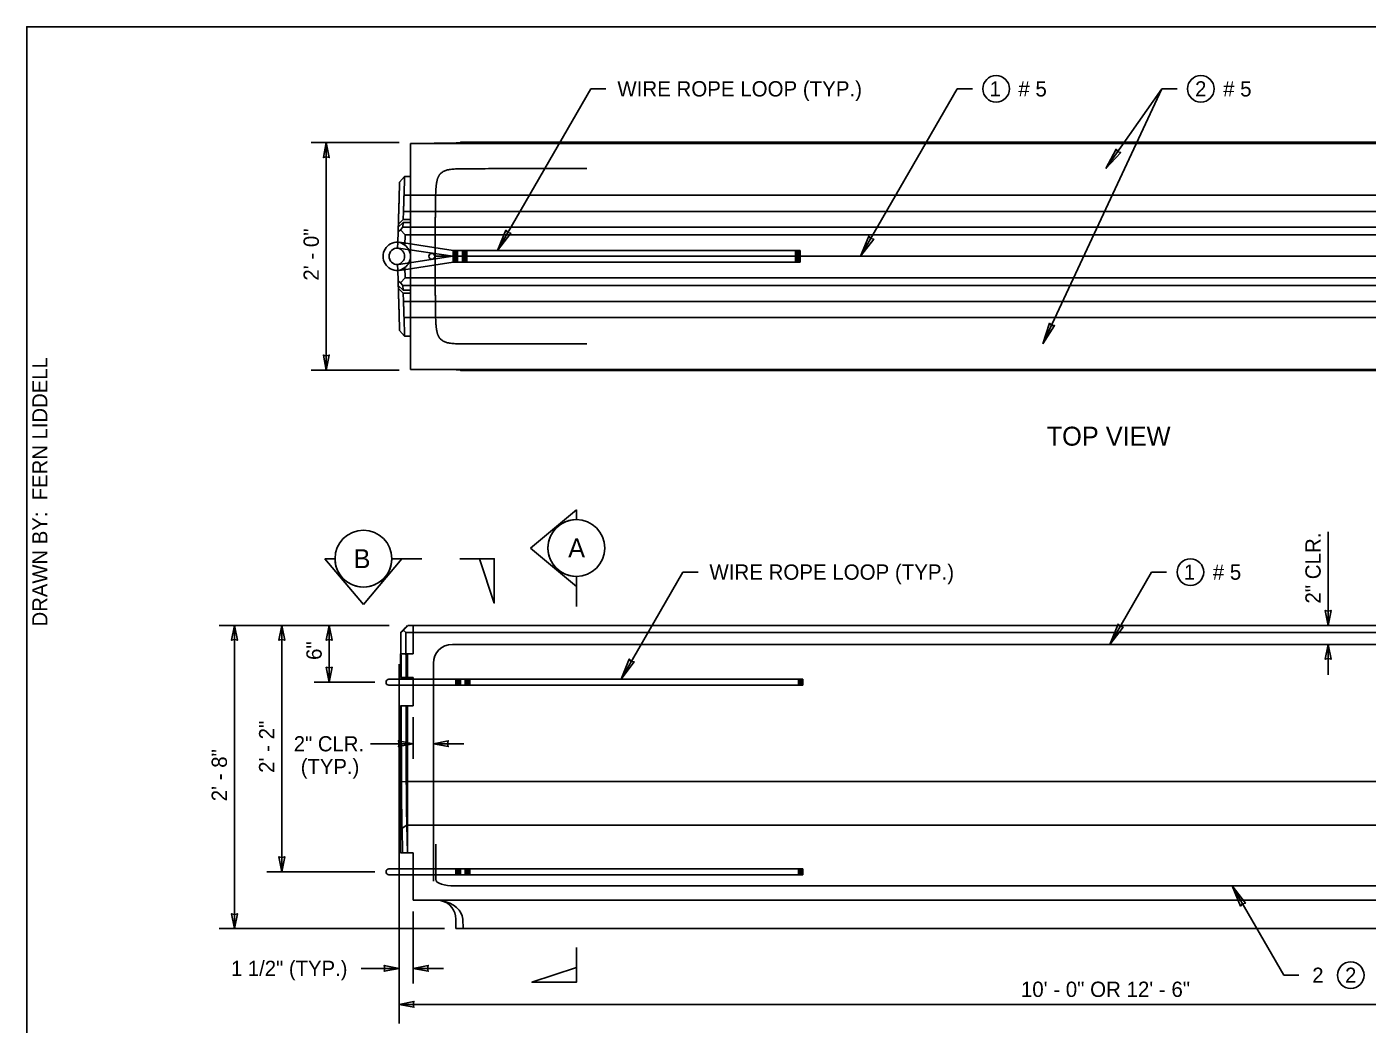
# Model space of a CAD drawing. Extents: x 99862 to 103680, y 99470 to 105076.
# Drawn here: x 99862 to 101262, y 101033 to 102076 of the extents above; entities that cross this region are included whole.
import ezdxf

# ---------------------------------------------------------------- set-up
doc = ezdxf.new("R2010")
doc.units = 0
for name, color, linetype in [('Level 1', 7, 'Continuous'), ('Level 15', 7, 'Continuous'), ('Level 17', 7, 'Continuous'), ('Level 20', 7, 'Continuous'), ('Level 27', 7, 'Continuous'), ('Level 62', 7, 'Continuous'), ('Level 9', 7, 'Continuous')]:
    doc.layers.add(name, color=color, linetype=linetype)

msp = doc.modelspace()

# ---------------------------------------------------------------- linework, layer by layer
at = {"layer": 'Level 1'}
for p, q in [((100262.8, 101919.2), (100262.8, 101953.7)), ((100251.5, 101913.2), (100251, 101895.4)), ((100256.6, 101919.2), (100251.5, 101913.2)), ((100256.1, 101899.4), (100256.6, 101919.2)), ((100256.6, 101919.2), (100262.8, 101919.2)), ((100255.3, 101874.2), (100255.5, 101882.6)), ((100250.1, 101866.1), (100249.9, 101861.2)), ((100255.2, 101871.1), (100250.1, 101866.1)), ((100250.2, 101869.3), (100250.1, 101866.1)), ((100250.4, 101877.6), (100250.2, 101869.3)), ((100250.2, 101869.3), (100255.3, 101874.2)), ((100255, 101866.2), (100252.5, 101863.4)), ((100255, 101866.2), (100255.2, 101871.1)), ((100255.2, 101871.1), (100262.8, 101871.1)), ((100262.8, 101874.2), (100255.3, 101874.2)), ((100262.8, 101871.1), (100262.8, 101874.2)), ((100249.6, 101850.4), (100249.9, 101861.2)), ((100249.9, 101861.2), (100252.5, 101863.4)), ((100252.5, 101863.4), (100257.3, 101858)), ((100257.3, 101858), (100257, 101847.5)), ((100249.6, 101850.4), (100249.4, 101844.2)), ((100249.6, 101820.9), (100249.4, 101827.2)), ((100257, 101823.9), (100257.3, 101813.4)), ((100249.9, 101810.2), (100249.6, 101820.9)), ((100249.9, 101810.2), (100250.1, 101805.2)), ((100252.5, 101807.9), (100249.9, 101810.2)), ((100252.5, 101807.9), (100257.3, 101813.4)), ((100250.2, 101802.1), (100250.1, 101805.2)), ((100255.2, 101800.3), (100250.1, 101805.2)), ((100250.2, 101802.1), (100250.4, 101793.7)), ((100250.2, 101802.1), (100255.3, 101797.1)), ((100255, 101805.2), (100252.5, 101807.9)), ((100255.2, 101800.3), (100255, 101805.2)), ((100262.8, 101800.3), (100255.2, 101800.3)), ((100255.5, 101788.8), (100255.3, 101797.1)), ((100255.3, 101797.1), (100262.8, 101797.1)), ((100262.8, 101797.1), (100262.8, 101800.3)), ((100251, 101776), (100251.5, 101758.2)), ((100256.6, 101752.2), (100256.1, 101771.9)), ((100256.6, 101752.2), (100251.5, 101758.2)), ((100262.8, 101752.2), (100256.6, 101752.2)), ((100262.8, 101717.6), (100262.8, 101752.2)), ((100255.5, 101445.2), (100260.3, 101450.1)), ((100260, 101450.1), (100260.3, 101450.1)), ((100252.9, 101442.7), (100252.6, 101442.7)), ((100255.5, 101445.2), (100252.9, 101442.7)), ((100258, 101442.7), (100255.5, 101445.2))]:
    msp.add_line(p, q, dxfattribs=at)
msp.add_lwpolyline([(99862, 99999.5), (103151, 99999.5), (103151, 102075.5), (99862, 102075.5)], close=True, dxfattribs=at)
for centre, radius, start, end in [((100249.2, 101835.7), 14.9, 88.3026, 271.6974), ((100249.2, 101835.7), 8.66, 88.3024, 180), ((100248, 101835.7), 8.66, 279.9067, 80.0933), ((100248, 101835.7), 14.8, 52.6201, 83.5248), ((100248, 101835.7), 14.8, 307.3799, 52.6201), ((100249.2, 101835.7), 8.66, 180, 271.6976), ((100248, 101835.7), 14.8, 276.4752, 307.3799)]:
    msp.add_arc(centre, radius, start, end, dxfattribs=at)
msp.add_ellipse((100250.9, 101441.4), major_axis=(-14.8, -14.8), ratio=0.014812, start_param=1.669, end_param=2.208388, dxfattribs=at)
for points in [[(100250.4, 101877.6), (100250.5, 101879.4), (100250.7, 101885.6), (100251, 101895.4)], [(100256.1, 101899.4), (100255.8, 101890.1), (100255.6, 101884.3), (100255.5, 101882.6)], [(100251, 101776), (100250.7, 101785.8), (100250.5, 101791.9), (100250.4, 101793.7)], [(100255.5, 101788.8), (100255.6, 101787.1), (100255.8, 101781.3), (100256.1, 101771.9)]]:
    msp.add_open_spline(points, degree=2, dxfattribs=at)
at = {"layer": 'Level 15'}
for p, q in [((100353.8, 101841.9), (100451.2, 102010.7)), ((100451.2, 102010.7), (100467.1, 102010.7)), ((100733, 101835.7), (100834, 102010.7)), ((100849.9, 102010.7), (100834, 102010.7)), ((100923.6, 101744.1), (101047.9, 102010.7)), ((100989.5, 101927.3), (101047.9, 102010.7)), ((101063.7, 102010.7), (101047.9, 102010.7)), ((100159.1, 101954.5), (100250.9, 101954.5)), ((100174.9, 101954.5), (100174.9, 101716.9)), ((100159.1, 101716.9), (100250.9, 101716.9)), ((101221.6, 101450.1), (101221.6, 101547.7)), ((100482.8, 101393.8), (100547.4, 101505.8)), ((100547.4, 101505.8), (100563.3, 101505.8)), ((100993.4, 101430.3), (101037.1, 101505.8)), ((101052.9, 101505.8), (101037.1, 101505.8)), ((100063.1, 101450.1), (100240.7, 101450.1)), ((100078.9, 101450.1), (100078.9, 101133.3)), ((100128.4, 101450.1), (100128.4, 101192.7)), ((100177.9, 101450.1), (100177.9, 101390.7)), ((101221.6, 101398.6), (101221.6, 101430.3)), ((100250.9, 101034.3), (100250.9, 101409.6)), ((100162.1, 101390.7), (100225.5, 101390.7)), ((100265.8, 101354.1), (100265.8, 101310.6)), ((100265.8, 101326.4), (100221.2, 101326.4)), ((100318.5, 101326.4), (100286.8, 101326.4)), ((100112.6, 101192.7), (100225.5, 101192.7)), ((101175.2, 101084.6), (101121.4, 101177.9)), ((100265.8, 101151.1), (100265.8, 101076)), ((100298.5, 101133.3), (100063.1, 101133.3)), ((100211.3, 101091.8), (100250.9, 101091.8)), ((100265.8, 101091.8), (100297.5, 101091.8)), ((101191, 101084.6), (101175.2, 101084.6)), ((100250.9, 101054.1), (101735.9, 101054.1))]:
    msp.add_line(p, q, dxfattribs=at)
for points in [[(100174.9, 101954.5), (100171.9, 101938.9), (100174.9, 101939.6), (100178, 101938.9)], [(100989.5, 101927.3), (101000, 101947.5), (101001.8, 101944.9), (101004.9, 101944.1)], [(100353.8, 101841.9), (100362.5, 101862.9), (100364.5, 101860.5), (100367.6, 101860)], [(100733, 101835.7), (100741.7, 101856.7), (100743.8, 101854.4), (100746.9, 101853.8)], [(100923.6, 101744.1), (100930.4, 101765.8), (100932.7, 101763.6), (100935.8, 101763.3)], [(100174.9, 101716.9), (100171.9, 101732.5), (100174.9, 101731.7), (100178, 101732.5)], [(101221.6, 101450.1), (101224.7, 101465.7), (101221.6, 101465), (101218.6, 101465.7)], [(100078.9, 101450.1), (100075.9, 101434.5), (100078.9, 101435.3), (100082, 101434.5)], [(100128.4, 101450.1), (100125.4, 101434.5), (100128.4, 101435.3), (100131.5, 101434.5)], [(100177.9, 101450.1), (100174.9, 101434.5), (100177.9, 101435.3), (100181, 101434.5)], [(100993.4, 101430.3), (101002.2, 101451.4), (101004.2, 101449), (101007.3, 101448.4)], [(101221.6, 101430.3), (101224.7, 101414.7), (101221.6, 101415.5), (101218.6, 101414.7)], [(100177.9, 101390.7), (100174.9, 101406.3), (100177.9, 101405.6), (100181, 101406.3)], [(100482.8, 101393.8), (100491.5, 101414.9), (100493.5, 101412.5), (100496.6, 101411.9)], [(100265.8, 101326.4), (100250.2, 101323.4), (100251, 101326.4), (100250.2, 101329.5)], [(100286.8, 101326.4), (100302.4, 101323.4), (100301.7, 101326.4), (100302.4, 101329.5)], [(100128.4, 101192.7), (100125.4, 101208.3), (100128.4, 101207.6), (100131.5, 101208.3)], [(101121.4, 101177.9), (101130.1, 101156.8), (101132.1, 101159.2), (101135.2, 101159.8)], [(100078.9, 101133.3), (100075.9, 101148.9), (100078.9, 101148.2), (100082, 101148.9)], [(100250.9, 101091.8), (100235.4, 101088.8), (100236.1, 101091.8), (100235.4, 101094.9)], [(100265.8, 101091.8), (100281.4, 101088.8), (100280.6, 101091.8), (100281.4, 101094.9)], [(100250.9, 101054.1), (100266.5, 101051.1), (100265.8, 101054.1), (100266.5, 101057.2)]]:
    msp.add_lwpolyline(points, close=True, dxfattribs=at)
at = {"layer": 'Level 17'}
for p, q in [((100287.7, 101953.7), (100262.8, 101953.7)), ((100287.7, 101953.7), (101699.2, 101953.7)), ((100314.6, 101954.6), (100315, 101955)), ((100315, 101955), (101671.9, 101955)), ((100255, 101866.3), (101731.9, 101866.3)), ((101729.6, 101858.1), (100257.3, 101858.1)), ((100257.3, 101813.3), (101729.6, 101813.3)), ((101731.9, 101805.1), (100255, 101805.1)), ((100287.7, 101717.6), (100262.8, 101717.6)), ((100287.7, 101717.6), (101699.2, 101717.6)), ((100314.6, 101716.8), (100315, 101716.4)), ((100315, 101716.4), (101671.9, 101716.4)), ((100260.3, 101450.1), (101726.6, 101450.1)), ((100252.6, 101442.7), (100252.6, 101420.4)), ((100252.9, 101442.7), (100253.1, 101395.7)), ((101728.9, 101442.7), (100258, 101442.7)), ((100258.2, 101395.7), (100258, 101442.7)), ((100252.6, 101420.4), (100252.4, 101420.4)), ((100252.4, 101420.4), (100252.4, 101395.7)), ((100240.4, 101393.8), (100253.9, 101393.8)), ((100252.4, 101395.7), (100253.1, 101395.7)), ((100258.2, 101395.7), (100253.1, 101395.7)), ((100265.8, 101393.8), (100253.9, 101393.8)), ((100265.8, 101395.7), (100258.2, 101395.7)), ((100265.8, 101366), (100265.8, 101395.7)), ((100253.9, 101387.6), (100240.4, 101387.6)), ((100253.9, 101387.6), (100265.8, 101387.6)), ((100253.2, 101366), (100252.4, 101366)), ((100252.4, 101366), (100252.4, 101212.5)), ((100253.2, 101366), (100258.3, 101366)), ((100253.2, 101366), (100253.4, 101286.5)), ((100258.3, 101366), (100265.8, 101366)), ((100258.5, 101287), (100258.3, 101366)), ((100258.5, 101287), (100253.4, 101286.5)), ((100259, 101241.3), (100254, 101238.4)), ((100254, 101238.4), (100254.5, 101212.5)), ((100259.6, 101212.5), (100259, 101241.3)), ((100252.4, 101212.5), (100254.5, 101212.5)), ((100259.6, 101212.5), (100254.5, 101212.5)), ((100265.8, 101212.5), (100259.6, 101212.5)), ((100265.8, 101163), (100265.8, 101212.5)), ((100240.4, 101195.8), (100253.9, 101195.8)), ((100265.8, 101195.8), (100253.9, 101195.8)), ((100253.9, 101189.6), (100240.4, 101189.6)), ((100253.9, 101189.6), (100265.8, 101189.6)), ((100290.5, 101163), (100265.8, 101163)), ((100290.5, 101163), (101696.3, 101163)), ((100310.3, 101133.3), (100310.3, 101143.2)), ((100317.4, 101143.2), (100317.8, 101133.3)), ((100317.8, 101133.3), (100310.3, 101133.3)), ((100317.8, 101133.3), (101669.1, 101133.3))]:
    msp.add_line(p, q, dxfattribs=at)
for centre, radius, start, end in [((100240.4, 101390.7), 3.09, 90, 270), ((100240.4, 101192.7), 3.09, 90, 270), ((100290.5, 101143.2), 19.8, 75.9627, 90), ((100290.5, 101143.2), 19.8, 0, 75.9627)]:
    msp.add_arc(centre, radius, start, end, dxfattribs=at)
for centre, major_axis, ratio, start_param, end_param in [((100287.7, 101954.6), (-19.9, 0), 0.041667, 1.570796, 1.815794), ((100286.5, 101954.6), (-28.1, 0), 0.029437, 1.786314, 3.112113), ((100287.7, 101716.8), (-19.9, 0), 0.041667, 4.467391, 4.712389), ((100286.5, 101716.8), (-28.1, 0), 0.029437, 3.171072, 4.496871), ((100289.4, 101143.2), (-28, 1.2), 0.705883, 3.200349, 4.526147)]:
    msp.add_ellipse(centre, major_axis=major_axis, ratio=ratio, start_param=start_param, end_param=end_param, dxfattribs=at)
for points in [[(100254, 101238.4), (100253.7, 101252.6), (100253.5, 101269.3), (100253.4, 101286.5)], [(100258.5, 101287), (100258.6, 101270.7), (100258.8, 101254.8), (100259, 101241.3)]]:
    msp.add_open_spline(points, degree=2, dxfattribs=at)
at = {"layer": 'Level 20'}
for centre in [(100874.7, 102010.7), (101088.6, 102010.7), (101077.7, 101505.8), (101245.2, 101084.6)]:
    msp.add_circle(centre, 13.9, dxfattribs=at)
at = {"layer": 'Level 27'}
for p, q in [((100256, 101899.7), (101730.9, 101899.7)), ((100255.5, 101882.7), (101731.4, 101882.7)), ((100255.5, 101788.6), (101731.4, 101788.6)), ((100256, 101771.7), (101730.9, 101771.7)), ((100258.5, 101287), (101728.4, 101287)), ((100259, 101241.3), (101727.8, 101241.3))]:
    msp.add_line(p, q, dxfattribs=at)
at = {"layer": 'Level 9'}
for p, q in [((100262.8, 101919.2), (100262.8, 101752.2)), ((100250.5, 101844.3), (100307.1, 101835.7)), ((100307.6, 101841.9), (100251.4, 101850.4)), ((100307.4, 101841.9), (100307.4, 101835.7)), ((100669.9, 101841.9), (100307.6, 101841.9)), ((100307.9, 101841.9), (100307.9, 101835.7)), ((100308.5, 101841.9), (100308.5, 101835.7)), ((100309.1, 101841.9), (100309.1, 101835.7)), ((100309.7, 101841.9), (100309.7, 101835.7)), ((100310.3, 101841.9), (100310.3, 101835.7)), ((100310.9, 101841.9), (100310.9, 101835.7)), ((100311.5, 101841.9), (100311.5, 101835.7)), ((100312.1, 101841.9), (100312.1, 101835.7)), ((100317.1, 101841.9), (100317.1, 101835.7)), ((100317.6, 101841.9), (100317.6, 101835.7)), ((100318.2, 101841.9), (100318.2, 101835.7)), ((100318.8, 101841.9), (100318.8, 101835.7)), ((100319.4, 101841.9), (100319.4, 101835.7)), ((100320, 101841.9), (100320, 101835.7)), ((100320.6, 101841.9), (100320.6, 101835.7)), ((100321.2, 101841.9), (100321.2, 101835.7)), ((100321.8, 101841.9), (100321.8, 101835.7)), ((100665.2, 101841.9), (100665.2, 101835.7)), ((100665.8, 101841.9), (100665.8, 101835.7)), ((100666.4, 101841.9), (100666.4, 101835.7)), ((100667, 101841.9), (100667, 101835.7)), ((100667.6, 101841.9), (100667.6, 101835.7)), ((100668.2, 101841.9), (100668.2, 101835.7)), ((100668.8, 101841.9), (100668.8, 101835.7)), ((100669.3, 101841.9), (100669.3, 101835.7)), ((100669.9, 101841.9), (100669.9, 101835.7)), ((100307, 101835.7), (100250.5, 101827.1)), ((100251.4, 101821), (100307.6, 101829.5)), ((100288.3, 101835.7), (101698.6, 101835.7)), ((100307.4, 101835.7), (100307.4, 101829.5)), ((100669.9, 101829.5), (100307.6, 101829.5)), ((100307.9, 101835.7), (100307.9, 101829.5)), ((100308.5, 101835.7), (100308.5, 101829.5)), ((100309.1, 101835.7), (100309.1, 101829.5)), ((100309.7, 101835.7), (100309.7, 101829.5)), ((100310.3, 101835.7), (100310.3, 101829.5)), ((100310.9, 101835.7), (100310.9, 101829.5)), ((100311.5, 101835.7), (100311.5, 101829.5)), ((100312.1, 101835.7), (100312.1, 101829.5)), ((100317.1, 101835.7), (100317.1, 101829.5)), ((100317.6, 101835.7), (100317.6, 101829.5)), ((100318.2, 101835.7), (100318.2, 101829.5)), ((100318.8, 101835.7), (100318.8, 101829.5)), ((100319.4, 101835.7), (100319.4, 101829.5)), ((100320, 101835.7), (100320, 101829.5)), ((100320.6, 101835.7), (100320.6, 101829.5)), ((100321.2, 101835.7), (100321.2, 101829.5)), ((100321.8, 101835.7), (100321.8, 101829.5)), ((100665.2, 101835.7), (100665.2, 101829.5)), ((100665.8, 101835.7), (100665.8, 101829.5)), ((100666.4, 101835.7), (100666.4, 101829.5)), ((100667, 101835.7), (100667, 101829.5)), ((100667.6, 101835.7), (100667.6, 101829.5)), ((100668.2, 101835.7), (100668.2, 101829.5)), ((100668.8, 101835.7), (100668.8, 101829.5)), ((100669.3, 101835.7), (100669.3, 101829.5)), ((100669.9, 101835.7), (100669.9, 101829.5)), ((100436.2, 101571), (100388.3, 101530.9)), ((100436.2, 101560.6), (100436.2, 101571)), ((100388.3, 101530.9), (100436.2, 101490.7)), ((100184, 101519.8), (100173.5, 101519.8)), ((100173.5, 101519.8), (100213.7, 101471.9)), ((100213.7, 101471.9), (100253.9, 101519.8)), ((100253.9, 101519.8), (100243.4, 101519.8)), ((100245, 101519.8), (100274.7, 101519.8)), ((100314.3, 101519.8), (100350.4, 101519.8)), ((100436.2, 101490.7), (100436.2, 101501.2)), ((100436.2, 101499.6), (100436.2, 101469.9)), ((100265.8, 101420.4), (100265.8, 101450.1)), ((100252.6, 101420.4), (100252.4, 101420.4)), ((100265.8, 101420.4), (100252.6, 101420.4)), ((100259.6, 101395.7), (100259.6, 101420.4)), ((100306.6, 101430.3), (101680.3, 101430.3)), ((100286.8, 101182.8), (100286.8, 101410.5)), ((100259.6, 101395.7), (100252.4, 101395.7)), ((100672.9, 101393.8), (100265.8, 101393.8)), ((100310.3, 101393.8), (100310.3, 101387.6)), ((100310.9, 101393.8), (100310.9, 101387.6)), ((100311.5, 101393.8), (100311.5, 101387.6)), ((100312.1, 101393.8), (100312.1, 101387.6)), ((100312.7, 101393.8), (100312.7, 101387.6)), ((100313.3, 101393.8), (100313.3, 101387.6)), ((100313.9, 101393.8), (100313.9, 101387.6)), ((100314.5, 101393.8), (100314.5, 101387.6)), ((100315.1, 101393.8), (100315.1, 101387.6)), ((100320, 101393.8), (100320, 101387.6)), ((100320.6, 101393.8), (100320.6, 101387.6)), ((100321.2, 101393.8), (100321.2, 101387.6)), ((100321.8, 101393.8), (100321.8, 101387.6)), ((100322.4, 101393.8), (100322.4, 101387.6)), ((100323, 101393.8), (100323, 101387.6)), ((100323.6, 101393.8), (100323.6, 101387.6)), ((100324.2, 101393.8), (100324.2, 101387.6)), ((100324.8, 101393.8), (100324.8, 101387.6)), ((100668.2, 101393.8), (100668.2, 101387.6)), ((100668.8, 101393.8), (100668.8, 101387.6)), ((100669.4, 101393.8), (100669.4, 101387.6)), ((100670, 101393.8), (100670, 101387.6)), ((100670.6, 101393.8), (100670.6, 101387.6)), ((100671.2, 101393.8), (100671.2, 101387.6)), ((100671.7, 101393.8), (100671.7, 101387.6)), ((100672.3, 101393.8), (100672.3, 101387.6)), ((100672.9, 101387.6), (100672.9, 101393.8)), ((100672.9, 101393.8), (100672.9, 101387.6)), ((100672.9, 101387.6), (100265.8, 101387.6)), ((100259.6, 101366), (100252.4, 101366)), ((100259.6, 101212.5), (100259.6, 101366)), ((100289.3, 101221.4), (100289.3, 101184.6)), ((100259.6, 101212.5), (100252.4, 101212.5)), ((100672.9, 101195.8), (100265.8, 101195.8)), ((100310.3, 101195.8), (100310.3, 101189.6)), ((100310.9, 101195.8), (100310.9, 101189.6)), ((100311.5, 101195.8), (100311.5, 101189.6)), ((100312.1, 101195.8), (100312.1, 101189.6)), ((100312.7, 101195.8), (100312.7, 101189.6)), ((100313.3, 101195.8), (100313.3, 101189.6)), ((100313.9, 101195.8), (100313.9, 101189.6)), ((100314.5, 101195.8), (100314.5, 101189.6)), ((100315.1, 101195.8), (100315.1, 101189.6)), ((100320, 101195.8), (100320, 101189.6)), ((100320.6, 101195.8), (100320.6, 101189.6)), ((100321.2, 101195.8), (100321.2, 101189.6)), ((100321.8, 101195.8), (100321.8, 101189.6)), ((100322.4, 101195.8), (100322.4, 101189.6)), ((100323, 101195.8), (100323, 101189.6)), ((100323.6, 101195.8), (100323.6, 101189.6)), ((100324.2, 101195.8), (100324.2, 101189.6)), ((100324.8, 101195.8), (100324.8, 101189.6)), ((100668.2, 101195.8), (100668.2, 101189.6)), ((100668.8, 101195.8), (100668.8, 101189.6)), ((100669.4, 101195.8), (100669.4, 101189.6)), ((100670, 101195.8), (100670, 101189.6)), ((100670.6, 101195.8), (100670.6, 101189.6)), ((100671.2, 101195.8), (100671.2, 101189.6)), ((100671.7, 101195.8), (100671.7, 101189.6)), ((100672.3, 101195.8), (100672.3, 101189.6)), ((100672.9, 101189.6), (100672.9, 101195.8)), ((100672.9, 101195.8), (100672.9, 101189.6)), ((100672.9, 101189.6), (100265.8, 101189.6)), ((100309.1, 101177.9), (101677.8, 101177.9)), ((100436.2, 101113.5), (100436.2, 101077.3))]:
    msp.add_line(p, q, dxfattribs=at)
for points in [[(100335.1, 101519.8), (100350.4, 101473.4), (100350.4, 101519.8)], [(100436.2, 101092.7), (100389.8, 101077.3), (100436.2, 101077.3)]]:
    msp.add_lwpolyline(points, close=True, dxfattribs=at)
for centre, radius in [((100285.2, 101835.7), 3.09), ((100436.2, 101530.9), 29.7), ((100213.7, 101519.8), 29.7)]:
    msp.add_circle(centre, radius, dxfattribs=at)
for centre, radius, start, end in [((100436.2, 101530.9), 29.7, 89.9978, 270.0022), ((100213.7, 101519.8), 29.7, 179.9978, 0.0022), ((100306.6, 101410.5), 19.8, 90, 180)]:
    msp.add_arc(centre, radius, start, end, dxfattribs=at)
msp.add_ellipse((100309.1, 101184.6), major_axis=(-19.8, 0), ratio=0.338238, start_param=0, end_param=1.570796, dxfattribs=at)
for points in [[(100288.8, 101835.7), (100288.8, 101872.2), (100288.8, 101908.6), (100288.8, 101927.3), (100308.6, 101927.3), (100322.8, 101927.3), (100447.1, 101927.3)], [(100288.8, 101835.6), (100288.8, 101799.2), (100288.8, 101762.7), (100288.8, 101744.1), (100308.6, 101744.1), (100322.8, 101744.1), (100447.1, 101744.1)]]:
    msp.add_open_spline(points, degree=4, dxfattribs=at)

# ---------------------------------------------------------------- texts
at = {"layer": 'Level 20'}
for s, height, p in [('WIRE ROPE LOOP (TYP.)', 16, (100479, 102002.7)), ('1', 15.8, (100867.9, 102002.8)), (' # 5', 16, (100892, 102002.7)), ('2', 15.8, (101082.6, 102002.8)), (' # 5', 16, (101105.9, 102002.7)), ('TOP VIEW', 19.8, (100927.5, 101637.9)), ('B', 19.8, (100203.4, 101509.9)), ('A', 19.8, (100427.6, 101521.1)), ('WIRE ROPE LOOP (TYP.)', 16, (100575.2, 101497.8)), ('1', 15.8, (101070.9, 101497.9)), (' # 5', 16, (101095.1, 101497.8)), ('(TYP.)', 15.84, (100148.2, 101294.7)), ('1 1/2" (TYP.)', 15.84, (100075.3, 101083.9)), ('2 ', 15.84, (101205, 101076.7)), ('2', 15.8, (101239.3, 101076.7)), ('10\' - 0" OR 12\' - 6"', 16, (100900.6, 101061.9))]:
    msp.add_text(s, height=height, dxfattribs=at).set_placement(p)
for s, height, rotation, p in [('2\' - 0"', 16, 90, (100167.1, 101810.3)), ('2" CLR.', 16, 90, (101213.8, 101472.9)), ('6"', 16, 90, (100170.1, 101414)), ('2\' - 2"', 16, 90, (100120.6, 101296)), ('2" CLR.', 15.84, 360, (100140.9, 101318.5)), ('2\' - 8"', 16, 90, (100071.1, 101266.3))]:
    msp.add_text(s, height=height, rotation=rotation, dxfattribs=at).set_placement(p)
at = {"layer": 'Level 62'}
msp.add_text('DRAWN BY:  FERN LIDDELL', height=15.84, rotation=90, dxfattribs=at).set_placement((99883.5, 101449))

doc.saveas('drawing.dxf')
